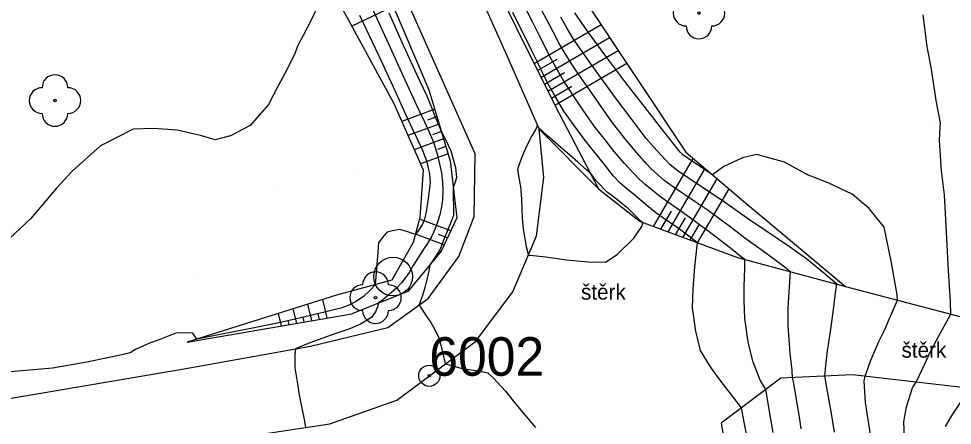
# Model space of a CAD drawing. Extents: x -448957 to -448612, y -1107690 to -1107245.
# Drawn here: x -448777.15 to -448740.89, y -1107383.27 to -1107367.47 of the extents above; entities that cross this region are included whole.
import ezdxf

# ---------------------------------------------------------------- set-up
doc = ezdxf.new("R2010")
doc.units = 0
for name, color, linetype in [('22', 7, 'Continuous'), ('63', 7, 'Continuous'), ('Default', 7, 'Continuous'), ('Vrstva 1', 7, 'Continuous'), ('Vrstva 10', 7, 'Continuous'), ('Vrstva 11', 7, 'Continuous'), ('Vrstva 14', 7, 'Continuous'), ('Vrstva 15', 7, 'Continuous'), ('Vrstva 16', 7, 'Continuous'), ('Vrstva 17', 7, 'Continuous'), ('Vrstva 22', 7, 'Continuous'), ('Vrstva 25', 7, 'Continuous'), ('Vrstva 40', 7, 'Continuous'), ('Vrstva 63', 7, 'Continuous')]:
    doc.layers.add(name, color=color, linetype=linetype)

# ---------------------------------------------------------------- blocks, each defined once
blk = doc.blocks.new('POINT_DISPLAY')
at = {"layer": 'Default'}
blk.add_line((0, 0), (0, 0), dxfattribs=at)
blk = doc.blocks.new('STROM$5')
at = {"layer": '22'}
blk.add_circle((0, 0), 0.5, dxfattribs=at)
for centre, start, end in [((0, 5), 0, 180), ((-5, 0), 90, 270), ((5, 0), 270, 90), ((0, -5), 180, 0)]:
    blk.add_arc(centre, 5, start, end, dxfattribs=at)
blk = doc.blocks.new('MEZNIK')
at = {"layer": 'Default'}
blk.add_circle((0, 0), 7.5, dxfattribs=at)
blk.add_blockref('POINT_DISPLAY', (0, 0), dxfattribs=at)
blk = doc.blocks.new('PPBP$7')
at = {"layer": '63'}
for radius in [4.12, 0.5]:
    blk.add_circle((0, 0), radius, dxfattribs=at)

msp = doc.modelspace()

# ---------------------------------------------------------------- linework, layer by layer
at = {"layer": 'Vrstva 10'}
for p, q in [((-448761.632, -1107361.251), (-448758.207, -1107368.874)), ((-448759.419, -1107372.726), (-448763.989, -1107362.47)), ((-448758.207, -1107368.874), (-448756.944, -1107371.765)), ((-448756.76, -1107373.647), (-448756.944, -1107371.765)), ((-448759.463, -1107375.154), (-448759.419, -1107372.726)), ((-448757.037, -1107375.905), (-448756.76, -1107373.647)), ((-448760.051, -1107376.712), (-448759.463, -1107375.154)), ((-448757.964, -1107378.086), (-448757.037, -1107375.905)), ((-448761.249, -1107378.341), (-448760.051, -1107376.712)), ((-448759.413, -1107380.01), (-448757.964, -1107378.086)), ((-448762.82, -1107379.476), (-448761.249, -1107378.341)), ((-448765.82, -1107380.198), (-448762.82, -1107379.476)), ((-448762.466, -1107382.289), (-448759.413, -1107380.01)), ((-448770.794, -1107381.085), (-448765.82, -1107380.198)), ((-448778.859, -1107382.461), (-448770.794, -1107381.085)), ((-448765.066, -1107383.214), (-448762.466, -1107382.289)), ((-448770.221, -1107383.984), (-448765.066, -1107383.214))]:
    msp.add_line(p, q, dxfattribs=at)
at = {"layer": 'Vrstva 11'}
for p, q in [((-448756.944, -1107371.765), (-448754.631, -1107374.079)), ((-448754.631, -1107374.079), (-448753.01, -1107375.36)), ((-448753.01, -1107375.36), (-448749.235, -1107376.758)), ((-448749.235, -1107376.758), (-448745.046, -1107377.875)), ((-448745.046, -1107377.875), (-448739.644, -1107379.291)), ((-448747.552, -1107381.445), (-448749.871, -1107383.186)), ((-448744.774, -1107381.304), (-448747.552, -1107381.445)), ((-448739.939, -1107381.871), (-448744.774, -1107381.304)), ((-448749.871, -1107383.186), (-448749.267, -1107386.764))]:
    msp.add_line(p, q, dxfattribs=at)
at = {"layer": 'Vrstva 14'}
for p, q in [((-448761.169, -1107360.877), (-448757.551, -1107368.4)), ((-448764.434, -1107362.701), (-448761.218, -1107370.239)), ((-448766.451, -1107363.624), (-448762.584, -1107370.769)), ((-448755.235, -1107366.651), (-448751.24, -1107372.666)), ((-448757.551, -1107368.4), (-448756.163, -1107371.155)), ((-448761.218, -1107370.239), (-448760.394, -1107372.991)), ((-448762.584, -1107370.769), (-448761.442, -1107373.35)), ((-448756.163, -1107371.155), (-448754.631, -1107374.079)), ((-448751.24, -1107372.666), (-448748.999, -1107374.559)), ((-448760.394, -1107372.991), (-448760.129, -1107375.213)), ((-448761.442, -1107373.35), (-448761.573, -1107375.2)), ((-448748.999, -1107374.559), (-448745.046, -1107377.875)), ((-448761.573, -1107375.2), (-448761.831, -1107376.175)), ((-448760.129, -1107375.213), (-448760.743, -1107376.5)), ((-448761.831, -1107376.175), (-448762.66, -1107377.639)), ((-448760.743, -1107376.5), (-448762.032, -1107378.072)), ((-448762.66, -1107377.639), (-448764.81, -1107378.215)), ((-448764.81, -1107378.215), (-448770.602, -1107380.039)), ((-448762.032, -1107378.072), (-448764.207, -1107378.937)), ((-448770.602, -1107380.039), (-448764.207, -1107378.937))]:
    msp.add_line(p, q, dxfattribs=at)
at = {"layer": 'Vrstva 15'}
for p, q in [((-448762.601, -1107366.997), (-448764.206, -1107367.772)), ((-448757.138, -1107369.219), (-448754.534, -1107367.706)), ((-448756.868, -1107369.756), (-448754.202, -1107368.207)), ((-448756.597, -1107370.293), (-448753.869, -1107368.707)), ((-448757.003, -1107369.488), (-448756.241, -1107369.045)), ((-448756.327, -1107370.83), (-448753.537, -1107369.208)), ((-448756.733, -1107370.024), (-448755.953, -1107369.571)), ((-448756.462, -1107370.561), (-448755.665, -1107370.098)), ((-448760.992, -1107370.994), (-448762.275, -1107371.467)), ((-448760.906, -1107371.282), (-448761.272, -1107371.417)), ((-448760.82, -1107371.57), (-448762.032, -1107372.017)), ((-448760.733, -1107371.858), (-448761.08, -1107371.985)), ((-448760.647, -1107372.146), (-448761.788, -1107372.567)), ((-448760.561, -1107372.434), (-448760.887, -1107372.554)), ((-448760.475, -1107372.721), (-448761.545, -1107373.117)), ((-448752.497, -1107375.55), (-448750.956, -1107372.906)), ((-448751.926, -1107375.761), (-448750.49, -1107373.299)), ((-448751.355, -1107375.973), (-448750.025, -1107373.692)), ((-448750.784, -1107376.184), (-448749.56, -1107374.086)), ((-448752.212, -1107375.656), (-448751.802, -1107374.952)), ((-448760.367, -1107375.711), (-448761.589, -1107375.262)), ((-448751.641, -1107375.867), (-448751.261, -1107375.216)), ((-448751.069, -1107376.079), (-448750.72, -1107375.479)), ((-448760.626, -1107376.255), (-448761.744, -1107375.845)), ((-448760.496, -1107375.983), (-448760.846, -1107375.855)), ((-448765.76, -1107379.205), (-448765.915, -1107378.563)), ((-448765.167, -1107379.102), (-448765.342, -1107378.382)), ((-448766.945, -1107379.409), (-448767.063, -1107378.924)), ((-448766.352, -1107379.307), (-448766.489, -1107378.744)), ((-448765.464, -1107379.154), (-448765.513, -1107378.948)), ((-448766.649, -1107379.358), (-448766.688, -1107379.197)), ((-448766.056, -1107379.256), (-448766.101, -1107379.072))]:
    msp.add_line(p, q, dxfattribs=at)
at = {"layer": 'Vrstva 16'}
for points in [[(-448746.763, -1107383.405), (-448746.835, -1107382.953), (-448746.896, -1107382.56), (-448746.969, -1107382.109), (-448747.053, -1107381.637), (-448747.106, -1107381.422), (-448747.114, -1107381.127), (-448747.187, -1107380.472), (-448747.264, -1107379.406), (-448747.275, -1107378.696), (-448747.275, -1107378.691), (-448747.176, -1107377.307), (-448747.491, -1107377.064), (-448748.281, -1107376.476), (-448748.948, -1107375.997), (-448749.424, -1107375.641), (-448750.03, -1107375.185), (-448750.415, -1107374.903), (-448750.84, -1107374.614), (-448751.286, -1107374.313), (-448751.688, -1107374.041), (-448752.081, -1107373.765), (-448752.34, -1107373.534), (-448752.587, -1107373.311), (-448752.768, -1107373.117), (-448753.146, -1107372.681), (-448753.614, -1107372.128), (-448754.112, -1107371.482), (-448754.833, -1107370.463), (-448755.506, -1107369.495), (-448755.92, -1107368.859), (-448756.16, -1107368.442), (-448756.4, -1107367.989), (-448757.074, -1107366.681)], [(-448763.908, -1107367.342), (-448763.18, -1107368.896), (-448762.605, -1107370.127), (-448762.26, -1107370.9), (-448762.066, -1107371.329), (-448761.875, -1107371.738), (-448761.668, -1107372.162), (-448761.475, -1107372.557), (-448761.31, -1107373.002), (-448761.195, -1107373.507), (-448761.176, -1107373.854), (-448761.21, -1107374.145), (-448761.246, -1107374.454), (-448761.287, -1107374.735), (-448761.34, -1107375.043), (-448761.4, -1107375.307), (-448761.482, -1107375.489), (-448761.554, -1107375.605), (-448761.661, -1107375.749), (-448761.741, -1107375.853), (-448761.746, -1107375.859), (-448761.749, -1107375.864), (-448761.999, -1107375.762), (-448762.346, -1107375.661), (-448762.641, -1107375.713), (-448762.843, -1107375.766), (-448762.88, -1107375.805), (-448763.039, -1107375.987), (-448763.171, -1107376.187), (-448763.202, -1107376.548), (-448763.268, -1107377.333), (-448763.309, -1107377.813), (-448763.516, -1107378.033), (-448763.754, -1107378.273), (-448764.047, -1107378.458), (-448764.348, -1107378.622), (-448764.635, -1107378.719), (-448765.644, -1107378.971), (-448767.029, -1107379.285), (-448768.074, -1107379.494), (-448769.384, -1107379.755), (-448770.227, -1107379.921), (-448770.385, -1107379.685), (-448771.017, -1107379.674), (-448771.732, -1107379.959), (-448772.068, -1107380.086), (-448772.332, -1107380.195), (-448772.606, -1107380.331), (-448772.816, -1107380.455), (-448773.253, -1107380.558), (-448774.496, -1107380.816), (-448775.84, -1107381.046), (-448777.459, -1107381.197)]]:
    msp.add_lwpolyline(points, dxfattribs=at)
at = {"layer": 'Vrstva 17'}
for points in [[(-448763.789, -1107366.262), (-448763.223, -1107367.496), (-448762.722, -1107368.601), (-448762.156, -1107369.846), (-448761.784, -1107370.66), (-448761.579, -1107371.084), (-448761.386, -1107371.476), (-448761.191, -1107371.911), (-448761.046, -1107372.268), (-448760.896, -1107372.722), (-448760.728, -1107373.459), (-448760.688, -1107373.83), (-448760.682, -1107374.146), (-448760.691, -1107374.511), (-448760.736, -1107374.786), (-448760.793, -1107375.094), (-448760.866, -1107375.342), (-448760.946, -1107375.557), (-448761.039, -1107375.786), (-448761.132, -1107375.98), (-448761.206, -1107376.095), (-448761.303, -1107376.241), (-448761.426, -1107376.428), (-448761.599, -1107376.702), (-448761.825, -1107377.069), (-448761.989, -1107377.334), (-448762.12, -1107377.51), (-448762.289, -1107377.733), (-448762.495, -1107377.96), (-448762.746, -1107378.181), (-448763.026, -1107378.406), (-448763.183, -1107378.53), (-448763.203, -1107378.64), (-448763.291, -1107378.857), (-448763.446, -1107379.081), (-448763.878, -1107379.345), (-448764.267, -1107379.508), (-448764.403, -1107379.557), (-448764.833, -1107379.705), (-448765.341, -1107379.888), (-448765.843, -1107380.071), (-448766.286, -1107380.243), (-448766.396, -1107380.301), (-448766.428, -1107380.524), (-448766.419, -1107381.036), (-448766.339, -1107381.578), (-448766.263, -1107382.088), (-448766.158, -1107382.609), (-448766.053, -1107383.114), (-448766.016, -1107383.356)], [(-448747.855, -1107383.554), (-448747.925, -1107383.1), (-448747.962, -1107382.893), (-448748.062, -1107382.339), (-448748.136, -1107381.884), (-448748.357, -1107381.518), (-448748.641, -1107380.784), (-448748.818, -1107380.032), (-448748.95, -1107379.117), (-448748.979, -1107378.408), (-448748.974, -1107377.878), (-448748.953, -1107377.18), (-448748.947, -1107376.835), (-448749.084, -1107376.735), (-448749.512, -1107376.394), (-448750.115, -1107375.919), (-448750.491, -1107375.635), (-448750.673, -1107375.503), (-448751.06, -1107375.222), (-448751.432, -1107374.954), (-448751.867, -1107374.651), (-448752.265, -1107374.373), (-448752.554, -1107374.143), (-448752.818, -1107373.92), (-448753.069, -1107373.699), (-448753.637, -1107373.091), (-448754.006, -1107372.651), (-448754.021, -1107372.633), (-448754.377, -1107372.187), (-448754.799, -1107371.649), (-448755.397, -1107370.778), (-448755.983, -1107369.899), (-448756.223, -1107369.479), (-448756.47, -1107369.032), (-448756.934, -1107368.116), (-448757.18, -1107367.618), (-448757.807, -1107366.383)], [(-448765.592, -1107367.113), (-448765.793, -1107367.528), (-448766.106, -1107368.128), (-448766.318, -1107368.538), (-448766.417, -1107368.797), (-448766.752, -1107369.492), (-448767.073, -1107370.083), (-448767.447, -1107370.806), (-448768.16, -1107371.629), (-448768.919, -1107372.027), (-448769.522, -1107372.176), (-448770.084, -1107372.015), (-448771, -1107371.803), (-448771.911, -1107371.735), (-448772.703, -1107371.771), (-448773.974, -1107372.418), (-448775.077, -1107373.394), (-448775.674, -1107374.063), (-448776.679, -1107375.235), (-448778.107, -1107376.566)], [(-448762.773, -1107367.252), (-448762.265, -1107368.385), (-448761.697, -1107369.629), (-448761.314, -1107370.45), (-448761.131, -1107370.889), (-448760.987, -1107371.258), (-448760.843, -1107371.603), (-448760.729, -1107371.872), (-448760.675, -1107371.967), (-448760.569, -1107372.172), (-448760.368, -1107372.613), (-448760.18, -1107373.26), (-448760.152, -1107373.648), (-448760.193, -1107373.82), (-448760.249, -1107373.962), (-448760.273, -1107374.003), (-448760.273, -1107374.199), (-448760.271, -1107374.443), (-448760.262, -1107374.763), (-448760.27, -1107375.123), (-448760.353, -1107375.36), (-448760.445, -1107375.574), (-448760.537, -1107375.805), (-448760.624, -1107376.02), (-448760.714, -1107376.254), (-448760.797, -1107376.459), (-448760.991, -1107376.751), (-448761.173, -1107377.022), (-448761.18, -1107377.033), (-448761.239, -1107377.332), (-448761.297, -1107377.61), (-448761.383, -1107377.918), (-448761.469, -1107378.225), (-448761.542, -1107378.429), (-448761.603, -1107378.597), (-448761.55, -1107378.68), (-448761.323, -1107379.015), (-448761.145, -1107379.273), (-448760.99, -1107379.546), (-448760.823, -1107379.899), (-448760.702, -1107380.377), (-448760.598, -1107380.812), (-448760.583, -1107380.883), (-448760.522, -1107380.9), (-448760.338, -1107380.951), (-448759.929, -1107381.058), (-448759.315, -1107381.154), (-448758.936, -1107381.23), (-448758.695, -1107381.449), (-448758.247, -1107381.942), (-448757.947, -1107382.321), (-448757.784, -1107382.531), (-448757.369, -1107383.022), (-448757.076, -1107383.355)], [(-448748.864, -1107383.741), (-448748.972, -1107383.15), (-448749.076, -1107382.589), (-448749.47, -1107382.088), (-448749.906, -1107381.511), (-448750.279, -1107381.005), (-448750.669, -1107380.369), (-448750.858, -1107379.614), (-448750.989, -1107378.698), (-448750.962, -1107377.982), (-448750.892, -1107377.121), (-448750.817, -1107376.397), (-448750.787, -1107376.183), (-448751.07, -1107375.965), (-448751.534, -1107375.618), (-448751.936, -1107375.34), (-448752.41, -1107375.011), (-448752.758, -1107374.737), (-448753.016, -1107374.506), (-448753.279, -1107374.289), (-448753.542, -1107374.066), (-448753.807, -1107373.85), (-448754.047, -1107373.587), (-448754.4, -1107373.14), (-448754.836, -1107372.597), (-448755.19, -1107372.151), (-448755.582, -1107371.621), (-448755.975, -1107371.062), (-448756.306, -1107370.51), (-448756.544, -1107370.083), (-448756.776, -1107369.625), (-448757.007, -1107369.161), (-448757.236, -1107368.701), (-448757.962, -1107367.229)], [(-448744.071, -1107383.633), (-448744.26, -1107382.388), (-448744.315, -1107381.538), (-448744.277, -1107381.362), (-448744.224, -1107381.215), (-448744.061, -1107380.734), (-448743.745, -1107380.021), (-448743.502, -1107379.525), (-448743.335, -1107379.12), (-448743.115, -1107378.618), (-448743.022, -1107378.405), (-448743.038, -1107378.2), (-448743.26, -1107376.954), (-448743.54, -1107375.578), (-448744.123, -1107374.848), (-448744.781, -1107374.294), (-448745.716, -1107373.851), (-448746.514, -1107373.546), (-448746.579, -1107373.499), (-448747.413, -1107373.052), (-448748.485, -1107372.748), (-448749.048, -1107372.885), (-448749.762, -1107373.222), (-448750.207, -1107373.539), (-448750.363, -1107373.437), (-448750.537, -1107373.322), (-448750.94, -1107373.051), (-448751.357, -1107372.761), (-448751.459, -1107372.654), (-448752.098, -1107371.859), (-448752.918, -1107370.809), (-448753.606, -1107369.912), (-448754.384, -1107368.875), (-448755.067, -1107367.955), (-448755.556, -1107367.254)], [(-448742.741, -1107384.008), (-448742.778, -1107383.14), (-448742.675, -1107382.551), (-448742.444, -1107381.821), (-448742.296, -1107381.595), (-448742.168, -1107381.324), (-448741.981, -1107380.91), (-448741.737, -1107380.403), (-448741.519, -1107379.984), (-448741.429, -1107379.823), (-448741.16, -1107379.333), (-448740.948, -1107378.949), (-448740.969, -1107378.467), (-448741.045, -1107377.259), (-448741.13, -1107375.528), (-448741.205, -1107374.32), (-448741.316, -1107373.382), (-448741.396, -1107372.211), (-448741.367, -1107371.688), (-448741.352, -1107371.518), (-448741.527, -1107370.65), (-448741.705, -1107369.433), (-448741.87, -1107368.553), (-448742.028, -1107367.321)], [(-448745.47, -1107383.539), (-448745.595, -1107382.733), (-448745.724, -1107382.017), (-448745.812, -1107381.584), (-448745.835, -1107381.428), (-448745.85, -1107381.359), (-448745.808, -1107380.943), (-448745.74, -1107380.366), (-448745.698, -1107380.128), (-448745.614, -1107379.55), (-448745.512, -1107378.769), (-448745.428, -1107378.138), (-448745.379, -1107377.786), (-448745.88, -1107377.36), (-448746.554, -1107376.804), (-448747.222, -1107376.342), (-448748.134, -1107375.722), (-448748.804, -1107375.265), (-448749.339, -1107374.89), (-448749.835, -1107374.537), (-448750.282, -1107374.236), (-448750.687, -1107373.969), (-448751.142, -1107373.669), (-448751.546, -1107373.4), (-448751.845, -1107373.155), (-448752.37, -1107372.602), (-448752.787, -1107372.126), (-448753.328, -1107371.408), (-448754.012, -1107370.495), (-448754.249, -1107370.175), (-448754.926, -1107369.23), (-448755.607, -1107368.271), (-448755.848, -1107367.854), (-448756.099, -1107367.41)], [(-448757.438, -1107376.326), (-448757.362, -1107376.628), (-448757.357, -1107376.643), (-448757.354, -1107376.65), (-448757.332, -1107376.658), (-448757.281, -1107376.666), (-448756.685, -1107376.724), (-448755.878, -1107376.849), (-448755.039, -1107376.918), (-448754.363, -1107376.932), (-448753.911, -1107376.632), (-448753.266, -1107376.003), (-448752.95, -1107375.542), (-448752.906, -1107375.399), (-448752.94, -1107375.376), (-448752.984, -1107375.345), (-448753.219, -1107375.113), (-448753.468, -1107374.867), (-448753.733, -1107374.652), (-448753.999, -1107374.433), (-448754.28, -1107374.224), (-448754.735, -1107373.767), (-448754.937, -1107373.495), (-448755.098, -1107373.346), (-448755.436, -1107373.05), (-448755.856, -1107372.692), (-448756.198, -1107372.389), (-448756.615, -1107372.028), (-448756.971, -1107371.685), (-448757.01, -1107371.615), (-448757.044, -1107371.716), (-448757.217, -1107372.023), (-448757.434, -1107372.433), (-448757.546, -1107372.697), (-448757.628, -1107372.897), (-448757.73, -1107373.165), (-448757.776, -1107373.35), (-448757.713, -1107373.718), (-448757.65, -1107374.083), (-448757.643, -1107374.147), (-448757.626, -1107374.488), (-448757.61, -1107374.884), (-448757.596, -1107375.226), (-448757.558, -1107375.629), (-448757.524, -1107375.891), (-448757.438, -1107376.326)], [(-448741.159, -1107383.321), (-448740.9, -1107382.883), (-448740.441, -1107382.18)]]:
    msp.add_lwpolyline(points, dxfattribs=at)

# ---------------------------------------------------------------- block references
at = {"layer": 'Vrstva 1', "xscale": 0.1, "yscale": 0.10000000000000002}
for p in [(-448757.551, -1107368.4), (-448758.207, -1107368.874), (-448761.218, -1107370.239), (-448775.739, -1107370.655), (-448762.584, -1107370.769), (-448756.163, -1107371.155), (-448756.163, -1107371.155), (-448756.944, -1107371.765), (-448756.944, -1107371.765), (-448759.419, -1107372.726), (-448751.24, -1107372.666), (-448760.394, -1107372.991), (-448761.442, -1107373.35), (-448756.76, -1107373.647), (-448754.631, -1107374.079), (-448754.631, -1107374.079), (-448748.999, -1107374.559), (-448748.999, -1107374.559), (-448761.573, -1107375.2), (-448760.129, -1107375.213), (-448759.463, -1107375.154), (-448753.01, -1107375.36), (-448757.037, -1107375.905), (-448761.831, -1107376.175), (-448760.743, -1107376.5), (-448760.051, -1107376.712), (-448749.235, -1107376.758), (-448762.66, -1107377.639), (-448745.046, -1107377.875), (-448745.046, -1107377.875), (-448764.81, -1107378.215), (-448762.032, -1107378.072), (-448757.964, -1107378.086), (-448761.249, -1107378.341), (-448764.207, -1107378.937), (-448764.207, -1107378.937), (-448762.82, -1107379.476), (-448770.602, -1107380.039), (-448770.602, -1107380.039), (-448759.413, -1107380.01), (-448765.82, -1107380.198), (-448770.794, -1107381.085), (-448770.794, -1107381.085), (-448747.552, -1107381.445), (-448744.774, -1107381.304), (-448762.466, -1107382.289), (-448765.066, -1107383.214), (-448749.871, -1107383.186)]:
    msp.add_blockref('POINT_DISPLAY', p, dxfattribs=at)
at = {"layer": 'Vrstva 14', "xscale": 0.1, "yscale": 0.10000000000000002}
for p in [(-448766.421, -1107368.402), (-448741.648, -1107371.636), (-448764.076, -1107373.415), (-448767.237, -1107373.949), (-448770.34, -1107377.42)]:
    msp.add_blockref('POINT_DISPLAY', p, dxfattribs=at)
at = {"layer": 'Vrstva 22', "xscale": 0.1, "yscale": 0.10000000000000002}
for p in [(-448750.732, -1107367.258), (-448775.739, -1107370.655), (-448763.291, -1107378.311)]:
    msp.add_blockref('STROM$5', p, dxfattribs=at)
at = {"layer": 'Vrstva 25', "xscale": 0.1, "yscale": 0.10000000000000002}
msp.add_blockref('MEZNIK', (-448762.61, -1107377.493), dxfattribs=at)
at = {"layer": 'Vrstva 63', "xscale": 0.1, "yscale": 0.10000000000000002}
msp.add_blockref('PPBP$7', (-448761.204, -1107381.347), dxfattribs=at)

# ---------------------------------------------------------------- texts
at = {"layer": 'Vrstva 40'}
for p in [(-448755.313, -1107378.389), (-448742.868, -1107380.643)]:
    msp.add_text('štěrk', height=0.6, dxfattribs=at).set_placement(p)
at = {"layer": 'Vrstva 63'}
msp.add_text('6002', height=1.5, dxfattribs=at).set_placement((-448761.204, -1107381.347))

doc.saveas('drawing.dxf')
